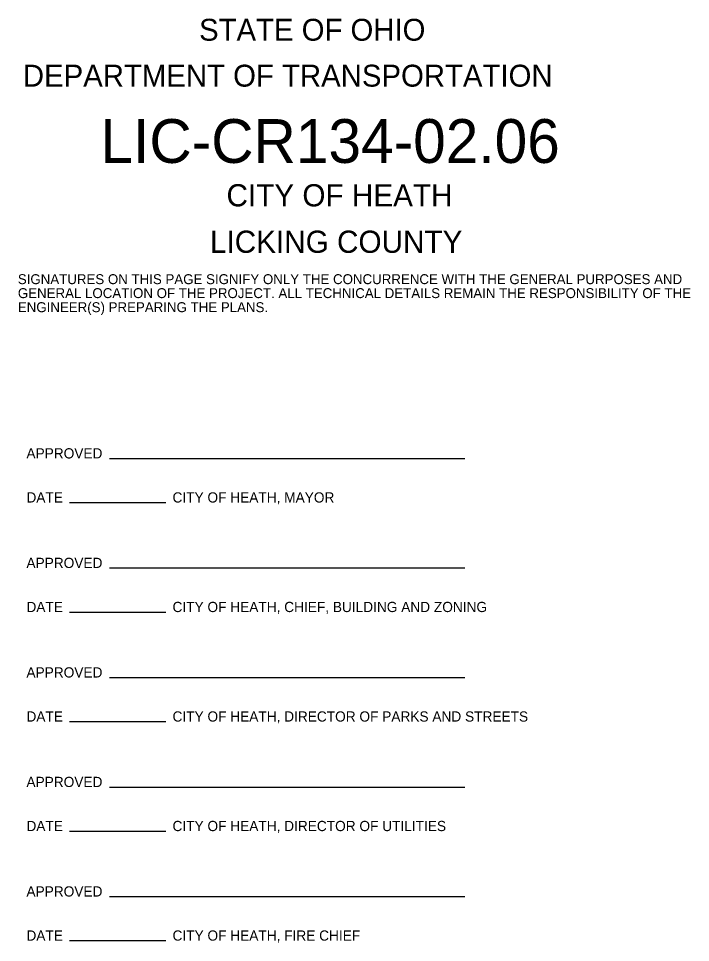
# Model space of a CAD drawing. Extents: x -38.3 to 52.8, y 6.3 to 33.6.
# Drawn here: x 1.87 to 9.23, y 11.12 to 21.25 of the extents above; entities that cross this region are included whole.
import ezdxf

# ---------------------------------------------------------------- set-up
doc = ezdxf.new("R2010")
doc.units = 0
doc.layers.add('SH_Data', color=7, linetype='Continuous')
doc.layers.add('SH_Text', color=7, linetype='Continuous')

msp = doc.modelspace()

# ---------------------------------------------------------------- linework, layer by layer
at = {"layer": 'SH_Data'}
for p, q in [((2.868, 16.426), (6.76, 16.426)), ((2.432, 15.943), (3.486, 15.943)), ((2.868, 15.226), (6.76, 15.226)), ((2.432, 14.743), (3.486, 14.743)), ((2.868, 14.026), (6.76, 14.026)), ((2.432, 13.543), (3.486, 13.543)), ((2.868, 12.826), (6.76, 12.826)), ((2.432, 12.343), (3.486, 12.343)), ((2.868, 11.626), (6.76, 11.626)), ((2.432, 11.143), (3.486, 11.143))]:
    msp.add_line(p, q, dxfattribs=at)

# ---------------------------------------------------------------- texts
for s, height, p in [('STATE OF OHIO', 0.24, (3.851, 21.003)), ('DEPARTMENT OF TRANSPORTATION', 0.24027, (1.921, 20.5)), ('LIC-CR134-02.06', 0.48, (2.771, 19.664)), ('CITY OF HEATH', 0.2432, (4.151, 19.188)), ('LICKING COUNTY', 0.2432, (3.97, 18.679)), ('SIGNATURES ON THIS PAGE SIGNIFY ONLY THE CONCURRENCE WITH THE GENERAL PURPOSES AND', 0.1088, (1.866, 18.336)), ('GENERAL LOCATION OF THE PROJECT. ALL TECHNICAL DETAILS REMAIN THE RESPONSIBILITY OF THE', 0.1088, (1.866, 18.183)), ('ENGINEER(S) PREPARING THE PLANS.', 0.1088, (1.866, 18.029)), ('APPROVED', 0.112, (1.96, 16.426)), ('DATE', 0.112, (1.96, 15.943)), ('APPROVED', 0.112, (1.96, 15.226)), ('DATE', 0.112, (1.96, 14.743)), ('APPROVED', 0.112, (1.96, 14.026)), ('DATE', 0.112, (1.96, 13.543)), ('APPROVED', 0.112, (1.96, 12.826)), ('DATE', 0.112, (1.96, 12.343)), ('APPROVED', 0.112, (1.96, 11.626)), ('DATE', 0.112, (1.96, 11.143))]:
    msp.add_text(s, height=height, dxfattribs=at).set_placement(p)
at = {"layer": 'SH_Text'}
for s, p in [('CITY OF HEATH, MAYOR', (3.56, 15.943)), ('CITY OF HEATH, CHIEF, BUILDING AND ZONING', (3.56, 14.743)), ('CITY OF HEATH, DIRECTOR OF PARKS AND STREETS', (3.56, 13.543)), ('CITY OF HEATH, DIRECTOR OF UTILITIES', (3.56, 12.343)), ('CITY OF HEATH, FIRE CHIEF', (3.56, 11.143))]:
    msp.add_text(s, height=0.112, dxfattribs=at).set_placement(p)

doc.saveas('drawing.dxf')
